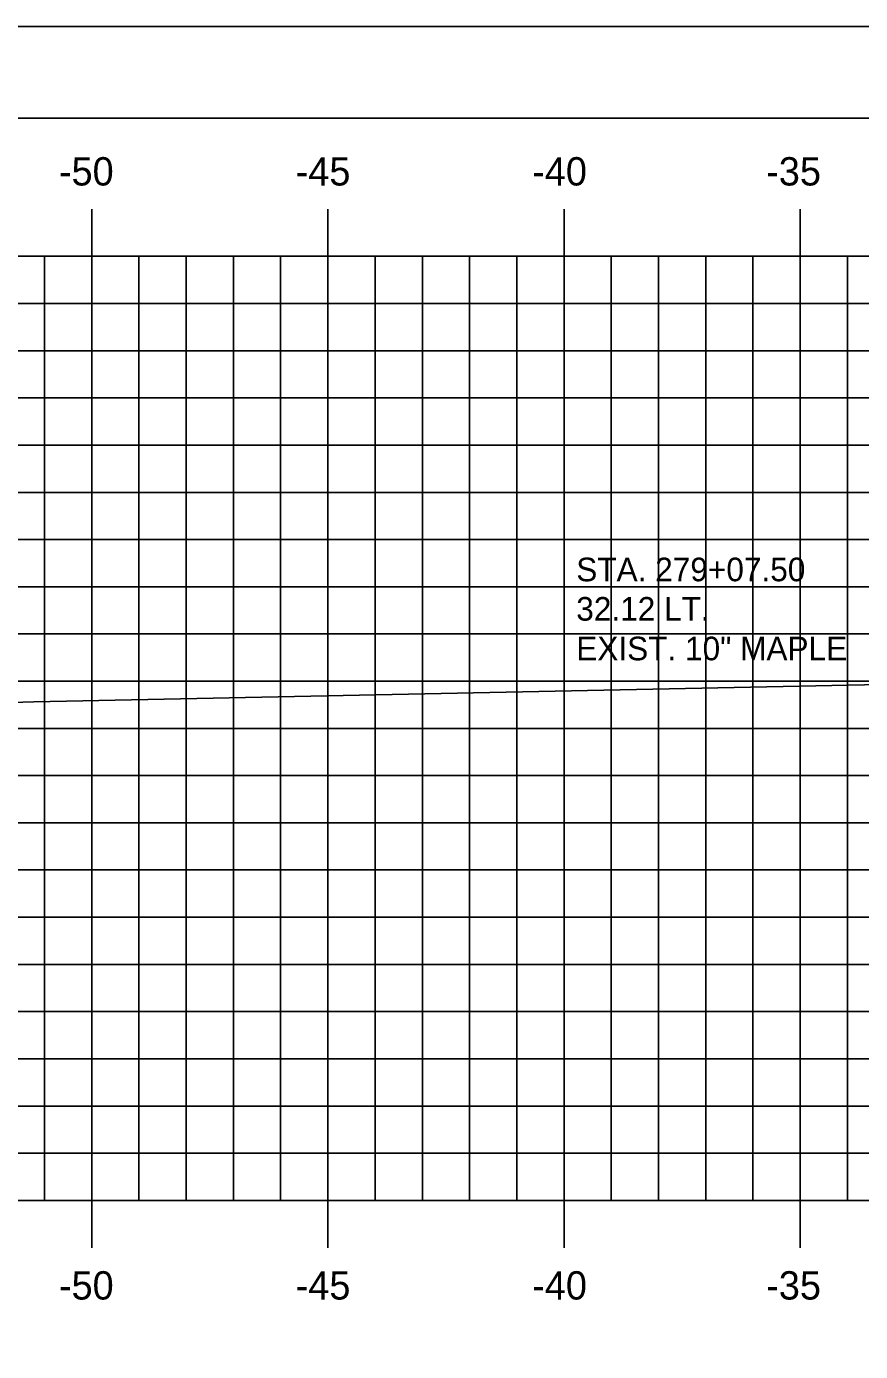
# Model space of a CAD drawing. Extents: x 854676 to 854846, y 366268 to 366378.
# Drawn here: x 854707.72 to 854725.38, y 366350.11 to 366378.18 of the extents above; entities that cross this region are included whole.
import ezdxf

# ---------------------------------------------------------------- set-up
doc = ezdxf.new("R2010")
doc.units = 0
for name, color, linetype in [('BORDER', 7, 'Continuous'), ('D_Text_Monospaced', 7, 'Continuous'), ('H_V ANNOTATION', 7, 'Continuous'), ('MAJOR', 7, 'Continuous'), ('MINOR', 7, 'Continuous'), ('PLOT BOUNDARY', 7, 'Continuous'), ('S_Roadway_Centerline', 7, 'Continuous')]:
    doc.layers.add(name, color=color, linetype=linetype)

msp = doc.modelspace()

# ---------------------------------------------------------------- linework, layer by layer
at = {"layer": 'BORDER'}
msp.add_line((854844.107, 366376.236), (854684.107, 366376.236), dxfattribs=at)
at = {"layer": 'MAJOR'}
for p, q in [((854709.106, 366374.311), (854709.106, 366373.309)), ((854714.106, 366374.311), (854714.106, 366373.309)), ((854719.106, 366374.311), (854719.106, 366373.309)), ((854724.106, 366374.311), (854724.106, 366373.309)), ((854689.106, 366373.309), (854829.106, 366373.309)), ((854689.106, 366373.309), (854829.106, 366373.309)), ((854709.106, 366353.309), (854709.106, 366373.309)), ((854714.106, 366353.309), (854714.106, 366373.309)), ((854719.106, 366353.309), (854719.106, 366373.309)), ((854724.106, 366353.309), (854724.106, 366373.309)), ((854689.106, 366368.309), (854829.106, 366368.309)), ((854689.106, 366363.309), (854829.106, 366363.309)), ((854689.106, 366358.309), (854829.106, 366358.309)), ((854689.106, 366353.309), (854829.106, 366353.309)), ((854689.106, 366353.309), (854829.106, 366353.309)), ((854709.106, 366352.307), (854709.106, 366353.309)), ((854714.106, 366352.307), (854714.106, 366353.309)), ((854719.106, 366352.307), (854719.106, 366353.309)), ((854724.106, 366352.307), (854724.106, 366353.309))]:
    msp.add_line(p, q, dxfattribs=at)
at = {"layer": 'MINOR'}
for p, q in [((854708.106, 366353.309), (854708.106, 366373.309)), ((854710.106, 366353.309), (854710.106, 366373.309)), ((854711.106, 366353.309), (854711.106, 366373.309)), ((854712.106, 366353.309), (854712.106, 366373.309)), ((854713.106, 366353.309), (854713.106, 366373.309)), ((854715.106, 366353.309), (854715.106, 366373.309)), ((854716.106, 366353.309), (854716.106, 366373.309)), ((854717.106, 366353.309), (854717.106, 366373.309)), ((854718.106, 366353.309), (854718.106, 366373.309)), ((854720.106, 366353.309), (854720.106, 366373.309)), ((854721.106, 366353.309), (854721.106, 366373.309)), ((854722.106, 366353.309), (854722.106, 366373.309)), ((854723.106, 366353.309), (854723.106, 366373.309)), ((854725.106, 366353.309), (854725.106, 366373.309)), ((854689.106, 366372.309), (854829.106, 366372.309)), ((854689.106, 366371.309), (854829.106, 366371.309)), ((854689.106, 366370.309), (854829.106, 366370.309)), ((854689.106, 366369.309), (854829.106, 366369.309)), ((854689.106, 366367.309), (854829.106, 366367.309)), ((854689.106, 366366.309), (854829.106, 366366.309)), ((854689.106, 366365.309), (854829.106, 366365.309)), ((854689.106, 366364.309), (854829.106, 366364.309)), ((854689.106, 366362.309), (854829.106, 366362.309)), ((854689.106, 366361.309), (854829.106, 366361.309)), ((854689.106, 366360.309), (854829.106, 366360.309)), ((854689.106, 366359.309), (854829.106, 366359.309)), ((854689.106, 366357.309), (854829.106, 366357.309)), ((854689.106, 366356.309), (854829.106, 366356.309)), ((854689.106, 366355.309), (854829.106, 366355.309)), ((854689.106, 366354.309), (854829.106, 366354.309))]:
    msp.add_line(p, q, dxfattribs=at)
at = {"layer": 'PLOT BOUNDARY'}
msp.add_lwpolyline([(854676.013, 366268.177), (854846.013, 366268.177), (854846.013, 366378.177), (854676.013, 366378.177)], close=True, dxfattribs=at)
at = {"layer": 'S_Roadway_Centerline'}
msp.add_lwpolyline([(854696.367, 366363.291), (854702.494, 366363.706), (854707.878, 366363.872), (854728.577, 366364.293), (854734.737, 366364.717), (854737.885, 366365.061), (854738.368, 366365.092), (854742.127, 366364.878), (854742.209, 366364.875), (854748.431, 366365.046), (854748.457, 366365.047), (854748.494, 366365.05), (854750.684, 366365.086), (854759.833, 366365.231), (854760.071, 366365.226), (854771.088, 366364.995)], dxfattribs=at)

# ---------------------------------------------------------------- texts
at = {"layer": 'D_Text_Monospaced'}
for s, height, p in [('STA. 279+07.50', 0.49998, (854719.365, 366366.425)), ('32.12 LT.', 0.5, (854719.365, 366365.591)), ('EXIST. 10" MAPLE', 0.49998, (854719.365, 366364.751))]:
    msp.add_text(s, height=height, dxfattribs=at).set_placement(p)
at = {"layer": 'H_V ANNOTATION'}
for s, p in [('-50', (854708.411, 366374.809)), ('-45', (854713.424, 366374.809)), ('-40', (854718.432, 366374.809)), ('-35', (854723.387, 366374.809)), ('-50', (854708.411, 366351.209)), ('-45', (854713.424, 366351.209)), ('-40', (854718.432, 366351.209)), ('-35', (854723.387, 366351.209))]:
    msp.add_text(s, height=0.6, dxfattribs=at).set_placement(p)

doc.saveas('drawing.dxf')
